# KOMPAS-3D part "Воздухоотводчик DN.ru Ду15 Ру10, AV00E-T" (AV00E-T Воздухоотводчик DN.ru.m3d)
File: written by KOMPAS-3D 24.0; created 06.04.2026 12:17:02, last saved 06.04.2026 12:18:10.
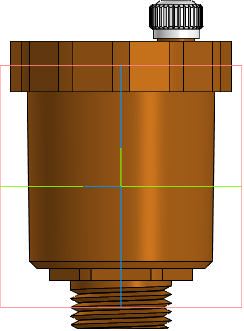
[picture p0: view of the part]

Document properties: Автор: R2D2; Полное имя файла: AV00E-T Воздухоотводчик DN.ru Ду15 Ру10.cdw

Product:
- Part/product: Воздухоотводчик DN.ru Ду15 Ру10  | designation AV00E-T
    Масса: 0.13
    Раздел спецификации: Прочие изделия
    Форматы листов документа: A4
    Примечание: D030-00297

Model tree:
1. Операция без истории:1

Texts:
  AV00E-T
